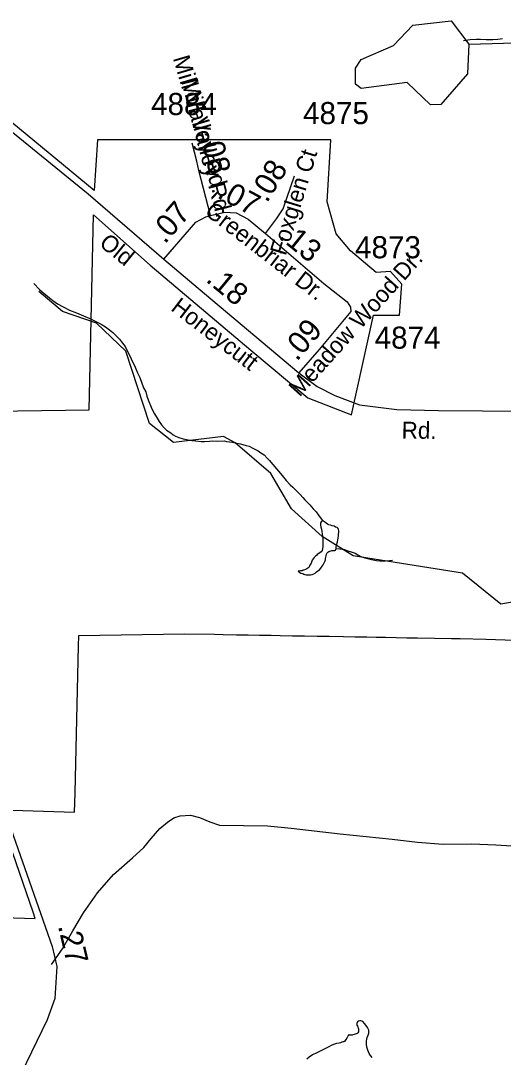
# Model space of a CAD drawing. Extents: x 2001466 to 2224147, y 644118 to 847247.
# Drawn here: x 2068297 to 2071024, y 663505 to 669368 of the extents above; entities that cross this region are included whole.
import ezdxf

# ---------------------------------------------------------------- set-up
doc = ezdxf.new("R2010")
doc.units = 0
for name, color, linetype in [('Exist Boundary Political City Limit New', 7, 'Continuous'), ('Exist Hydrographic Creek Single Shore', 7, 'Continuous'), ('Exist Hydrographic Misc Water Feature', 7, 'Continuous'), ('Exist Road Non-System Type 51', 7, 'Continuous'), ('Exist Road Non-System Type 51 Label', 7, 'Continuous'), ('Exist Road Secondary Mileage Hundredths English Label', 7, 'Continuous'), ('Exist Road Secondary Type 51 Attributed', 7, 'Continuous'), ('Exist Road Secondary Type 51 Label', 7, 'Continuous'), ('Exist Road Secondary Type 51 Number Label', 7, 'Continuous'), ('Map Preparation Boundary City Limit Buffer Line', 7, 'Continuous')]:
    doc.layers.add(name, color=color, linetype=linetype)

msp = doc.modelspace()

# ---------------------------------------------------------------- linework, layer by layer
at = {"layer": 'Exist Boundary Political City Limit New'}
for points in [[(2070028.4, 668344), (2070050.2, 668694), (2068729.9, 668694), (2068710.9, 668408.2), (2068202, 668828.1)], [(2067739.9, 667154.2), (2068682.6, 667166.9), (2068708, 668269.6), (2069029, 667985.2), (2069598, 667503.9), (2069919, 667234.1), (2070167, 667139.3), (2070291, 667702.2), (2070436.9, 667702.2), (2070451.5, 667877.3), (2070385.9, 667950.2), (2070305.6, 667942.9), (2070159.6, 668066.9), (2070079.4, 668161.7), (2070028.4, 668344)], [(2068249.8, 664902.3), (2068601.1, 664891.6), (2068603.8, 665000), (2068614, 665416.3), (2068623.9, 665830), (2068624.9, 665890), (2069222.4, 665900.2), (2069391.6, 665897.2), (2069441.6, 665896.4), (2069516.6, 665895), (2069581.6, 665893.9), (2069646.6, 665892.8), (2069711.5, 665891.6), (2069762.4, 665890.7), (2069832.5, 665889.4), (2069899.9, 665888.2), (2069972.5, 665887), (2070040.6, 665885.8), (2070121.1, 665884.4), (2070186.2, 665883.2), (2070252.1, 665882.1), (2070304.6, 665881.1), (2070357.5, 665880.2), (2070417.9, 665879.1), (2070478.4, 665878.1), (2070538.9, 665876.9), (2070730.5, 665873.6), (2070780.8, 665872.7), (2070926.2, 665870.1), (2071419.1, 665853.6)], [(2067655.1, 664312.7), (2068378.8, 664290), (2068367, 664325.9), (2068251.6, 664659.2)]]:
    msp.add_lwpolyline(points, dxfattribs=at)
at = {"layer": 'Exist Hydrographic Creek Single Shore'}
msp.add_lwpolyline([(2071243.2, 666109.3), (2071010, 666068.1), (2070793.1, 666243.1), (2070176.1, 666340.9), (2070001.2, 666449.5), (2069826.1, 666607.3), (2069709.2, 666806.5), (2069508.2, 666981.1), (2069442.2, 667015.3), (2069159.2, 666981.7), (2069025.1, 667089.4), (2068891.2, 667498.9), (2068724.1, 667656.6), (2068532.2, 667722.7), (2068399.1, 667837)], dxfattribs=at)
at = {"layer": 'Exist Hydrographic Misc Water Feature'}
msp.add_line((2070829.2, 669234.5), (2071504.2, 669253.6), dxfattribs=at)
for points in [[(2070829.2, 669234.5), (2070821.2, 669067.3), (2070671.3, 668893.2), (2070613.3, 668891.1), (2070480.2, 669018.5), (2070221.2, 668984.3), (2070188.2, 669008), (2070188.2, 669099.8), (2070221.2, 669148.4), (2070404.3, 669226.7), (2070512.2, 669342.6), (2070729.3, 669367.7), (2070829.2, 669234.5)], [(2070799, 669256.8), (2070837.2, 669260.7), (2070873.3, 669263), (2070894.8, 669262.9), (2070926.8, 669260.9), (2070948.9, 669260.8), (2070965.1, 669260.8), (2070993, 669263), (2071018.9, 669267.2)], [(2068370, 667880.5), (2068402.2, 667848.4), (2068418, 667834.6), (2068458.4, 667800.6), (2068478.3, 667784.6), (2068504.1, 667766.9), (2068536.3, 667748.6), (2068572.2, 667731), (2068612.4, 667714.7), (2068650.5, 667698.8), (2068686.6, 667683.2), (2068720.4, 667667.2), (2068750.6, 667651.2), (2068776.2, 667637.2), (2068798.4, 667619.2), (2068816.6, 667603.5), (2068836.5, 667585.5), (2068854.7, 667567.3), (2068872.4, 667543.5), (2068886.3, 667525.6), (2068898.6, 667501.4), (2068914.4, 667469.4), (2068926.7, 667441.6), (2068938.6, 667417.5), (2068946.6, 667399.6), (2068957.1, 667375.7), (2068969, 667349.6), (2068991.1, 667291.9), (2069002.8, 667267.8), (2069008.9, 667243.8), (2069017.1, 667223.9), (2069033.1, 667181.7), (2069041.1, 667165.9), (2069053.2, 667143.8), (2069067, 667119.8), (2069079.5, 667100), (2069091.4, 667082.1), (2069107.4, 667064.2), (2069121.1, 667052), (2069145.3, 667036.1), (2069157.2, 667026.2), (2069171.1, 667018), (2069189.4, 667010), (2069215.2, 667002.4), (2069243.7, 666996.5), (2069263.2, 666994.3), (2069285.1, 666990.6), (2069315.5, 666988.4), (2069335.4, 666988.2), (2069363.3, 666990.5), (2069383.2, 666992.4), (2069409.2, 666990.4), (2069447.1, 666990.8), (2069459.4, 666988.5), (2069493.3, 666984.6), (2069517.5, 666978.9), (2069539.2, 666974.8), (2069571.2, 666965.1), (2069587.6, 666961), (2069609.3, 666950.8), (2069637.6, 666935.1), (2069653.4, 666923), (2069671.5, 666913), (2069689.3, 666893.2), (2069701.8, 666881.2), (2069709.4, 666871.2), (2069721.5, 666857.1)], [(2069721.5, 666857.1), (2069773.8, 666795.3), (2069797.6, 666767.3), (2069819.9, 666743.3), (2069833.7, 666729.4), (2069855.8, 666709.4), (2069875.7, 666687.4), (2069890.1, 666671.4), (2069902.2, 666657.4), (2069929.8, 666629.7), (2069949.9, 666607.6), (2069965.9, 666589.7), (2069980.1, 666571.8), (2069989.9, 666557.7), (2070001.5, 666541.3), (2070004.1, 666537.7)], [(2070004.1, 666537.7), (2070001.5, 666541.3), (2069994.2, 666533.9), (2069991.8, 666527.8), (2069990.3, 666515.9), (2069992.2, 666503.8), (2069996.1, 666491.9), (2069997.9, 666477.8), (2070000.2, 666463.7), (2070002.2, 666452), (2070004.5, 666439.9), (2070004.5, 666429.8), (2070004.1, 666418), (2070004.3, 666403.8), (2070004.3, 666393.7), (2070002.4, 666379.7), (2070000.4, 666372), (2069994.2, 666364), (2069982.3, 666353.6), (2069972.5, 666347.8), (2069968.4, 666343.6), (2069962.6, 666339.6), (2069954.4, 666331.9), (2069948.5, 666323.9), (2069944.6, 666315.9), (2069940.3, 666305.6), (2069938.4, 666299.8), (2069934.5, 666293.5), (2069930.4, 666287.6), (2069928.8, 666281.8), (2069924.3, 666275.6), (2069918.6, 666271.6), (2069912.8, 666267.6), (2069906.7, 666263.7), (2069896.6, 666259.5), (2069892.7, 666259.7), (2069886.6, 666255.8), (2069878.6, 666255.8), (2069872.6, 666253.8), (2069864.4, 666253.4), (2069868.5, 666249.6), (2069880.6, 666243.7), (2069890.7, 666241.8), (2069896.6, 666237.6), (2069902.8, 666235.5), (2069910.6, 666233.9), (2069918.6, 666233.9), (2069924.5, 666233.8), (2069934.8, 666233.9), (2069944.4, 666235.6), (2069952.8, 666239.6), (2069960.6, 666243.7), (2069968.4, 666249.8), (2069976.6, 666255.9), (2069984.6, 666262), (2069992.6, 666271.8), (2070000.6, 666281.9), (2070006.5, 666289.9), (2070008.8, 666297.7), (2070012.7, 666306), (2070016.6, 666311.9), (2070018.4, 666317.7), (2070018.4, 666325.8), (2070020.3, 666334.1), (2070022.5, 666341.9), (2070024.4, 666350.1), (2070028.5, 666358), (2070032.2, 666361.9), (2070038.3, 666365.8), (2070048.4, 666370), (2070054.7, 666371.9), (2070066.6, 666372.1), (2070072.5, 666372), (2070076.2, 666373.9), (2070078.5, 666382.1)], [(2070078.5, 666382.1), (2070080.3, 666387.8), (2070082.2, 666401.7), (2070086.5, 666419.8), (2070088.5, 666432), (2070090.2, 666441.9), (2070092, 666455.8), (2070092, 666463.9), (2070094.1, 666473.8), (2070094.3, 666481.9), (2070092.2, 666489.9), (2070090.2, 666495.9), (2070084.4, 666502), (2070076.2, 666504.1), (2070068.4, 666508.1), (2070055.9, 666510), (2070048.1, 666514), (2070038.3, 666515.9), (2070030.1, 666520), (2070022.1, 666526.1), (2070014.1, 666533.7), (2070010, 666538), (2070004.1, 666537.7)], [(2070078.5, 666382.1), (2070100.2, 666380), (2070126.3, 666376), (2070146.2, 666370.2), (2070164.4, 666364.2), (2070186.4, 666356.4), (2070202.1, 666346.3), (2070218.1, 666338.1), (2070230.2, 666334.3), (2070242.3, 666330.4), (2070264.3, 666324.2), (2070278.6, 666320.5), (2070306.5, 666314.2), (2070326.6, 666312.4), (2070342.4, 666312.4), (2070358.4, 666312.4), (2070380.5, 666314.4), (2070398.2, 666316.5)], [(2070283.8, 663502.9), (2070275.1, 663513.1), (2070267.6, 663522.8), (2070261.4, 663535.1), (2070257.5, 663545), (2070253.4, 663561), (2070251.4, 663578.8), (2070251.6, 663595), (2070253.4, 663606.8), (2070255.3, 663617.1), (2070259.4, 663629.1), (2070263.5, 663641), (2070263.2, 663650.8), (2070263.5, 663658.9), (2070261, 663664.9), (2070257.3, 663672.8), (2070253.2, 663679.1), (2070239.3, 663694.9), (2070229.4, 663707), (2070219.4, 663710.9), (2070213.4, 663710.6), (2070205.4, 663708.6), (2070199.3, 663704.7), (2070195.4, 663696.7), (2070195.4, 663686.6), (2070199.5, 663680.7), (2070201.1, 663674.8), (2070203.4, 663670.8), (2070205.2, 663664.8), (2070205.2, 663656.7), (2070205.6, 663649), (2070201.1, 663642.7), (2070197.6, 663638.8), (2070187.6, 663634.7), (2070181.2, 663632.8), (2070173.2, 663630.8), (2070169.3, 663630.5), (2070161.3, 663630.5), (2070155.4, 663630.6), (2070151.5, 663632.8), (2070147.4, 663628.6), (2070143.1, 663620.7), (2070139.2, 663612.8), (2070133.2, 663604.8), (2070129.3, 663596.8), (2070123.6, 663592.8), (2070119.3, 663592.7), (2070111.3, 663590.6), (2070103.5, 663586.6), (2070095.5, 663584.5), (2070081.6, 663582.6), (2070065.2, 663576.5), (2070051.4, 663570.5), (2070037.3, 663564.5), (2070027.2, 663558.4), (2070015.8, 663552.4), (2070001.2, 663544.5), (2069969.4, 663530.2), (2069945.4, 663518.5), (2069927.6, 663506.1), (2069913.8, 663494.5)]]:
    msp.add_lwpolyline(points, dxfattribs=at)
at = {"layer": 'Exist Road Non-System Type 51'}
msp.add_lwpolyline([(2068470.8, 664030.3), (2068532.6, 664119), (2068590.6, 664219.9), (2068650.7, 664322.6), (2068731, 664435), (2068821.1, 664539.2), (2068929.1, 664633), (2068992.3, 664691.7), (2069033.3, 664742.9), (2069082.4, 664797.9), (2069125.2, 664835), (2069161.6, 664858.3), (2069197.9, 664869.5), (2069256, 664874.3), (2069307.7, 664861.3), (2069365.2, 664836.1), (2069420.8, 664817), (2069690.7, 664813.5), (2069824.5, 664800.8), (2070101.8, 664769.2), (2070395.2, 664739.2), (2070538.9, 664722.3), (2070684.6, 664709.3), (2070846.7, 664712.1), (2070982.6, 664707.3), (2071132.3, 664696.3)], dxfattribs=at)
at = {"layer": 'Exist Road Secondary Type 51 Attributed'}
for points in [[(2067446.5, 669206.9), (2067504.2, 669211), (2067569.6, 669203.7), (2067677, 669168.8), (2067771.4, 669122.4), (2067832.4, 669073), (2067915.1, 669006.1), (2068261.4, 668727.3), (2068676.8, 668389.3)], [(2067446.5, 669206.9), (2067474, 669004.1), (2067515.1, 668668.2), (2067591.1, 668254.1), (2067645, 667943.6), (2067664, 667761.9), (2067661.9, 667400.6), (2067667.1, 667003.5), (2067705.1, 666671.8), (2067786.4, 666166.9), (2067860.3, 665913.4), (2068216, 664867.7), (2068474.6, 664130.4), (2068499.9, 664018.4), (2068495.7, 663927.6), (2068489.4, 663836.8), (2068445.1, 663716.3), (2068298.3, 663412.1)], [(2069369.7, 668265.9), (2069356.4, 668317), (2069343, 668368), (2069316.6, 668470.3), (2069303.7, 668521.4), (2069291, 668572.7), (2069278.8, 668624), (2069265.1, 668675)], [(2069679.5, 668163.3), (2069741.8, 668246.7), (2069779.8, 668303.7), (2069843.1, 668489.6)], [(2068676.8, 668389.3), (2069104.8, 668018.5)], [(2069104.8, 668018.5), (2069286.3, 668228.7), (2069343.3, 668259.4), (2069369.7, 668265.9)], [(2069369.7, 668265.9), (2069450.5, 668285.8), (2069514.8, 668280.5), (2069581.3, 668244.6), (2069679.5, 668163.3)], [(2069679.5, 668163.3), (2070010.4, 667881.2), (2070142.4, 667777.7), (2070160.3, 667747.1)], [(2069104.8, 668018.5), (2069335.4, 667824.2), (2069869, 667376.3)], [(2070160.3, 667747.1), (2070161.4, 667722.8), (2069984, 667508.4), (2069869, 667376.3)], [(2069869, 667376.3), (2069971.9, 667298.2), (2070071.1, 667247.5), (2070210.4, 667194.7), (2070421.5, 667169.3), (2070658, 667163), (2071402.1, 667156.6)]]:
    msp.add_lwpolyline(points, dxfattribs=at)
at = {"layer": 'Map Preparation Boundary City Limit Buffer Line'}
for points in [[(2070028.4, 668344), (2070050.2, 668694), (2068729.9, 668694), (2068710.9, 668408.2), (2068202, 668828.1)], [(2067739.9, 667154.2), (2068682.6, 667166.9), (2068708, 668269.6), (2069029, 667985.2), (2069598, 667503.9), (2069919, 667234.1), (2070167, 667139.3), (2070291, 667702.2), (2070436.9, 667702.2), (2070451.5, 667877.3), (2070385.9, 667950.2), (2070305.6, 667942.9), (2070159.6, 668066.9), (2070079.4, 668161.7), (2070028.4, 668344)], [(2068249.8, 664902.3), (2068601.1, 664891.6), (2068603.8, 665000), (2068614, 665416.3), (2068623.9, 665830), (2068624.9, 665890), (2069222.4, 665900.2), (2069391.6, 665897.2), (2069441.6, 665896.4), (2069516.6, 665895), (2069581.6, 665893.9), (2069646.6, 665892.8), (2069711.5, 665891.6), (2069762.4, 665890.7), (2069832.5, 665889.4), (2069899.9, 665888.2), (2069972.5, 665887), (2070040.6, 665885.8), (2070121.1, 665884.4), (2070186.2, 665883.2), (2070252.1, 665882.1), (2070304.6, 665881.1), (2070357.5, 665880.2), (2070417.9, 665879.1), (2070478.4, 665878.1), (2070538.9, 665876.9), (2070730.5, 665873.6), (2070780.8, 665872.7), (2070926.2, 665870.1), (2071419.1, 665853.6)], [(2067655.1, 664312.7), (2068378.8, 664290), (2068367, 664325.9), (2068251.6, 664659.2)]]:
    msp.add_lwpolyline(points, dxfattribs=at)

# ---------------------------------------------------------------- texts
at = {"layer": 'Exist Road Non-System Type 51 Label'}
msp.add_text('Mill Valley Rd.', height=95, rotation=286.38458, dxfattribs=at).set_placement((2069156.1, 669156.4))
at = {"layer": 'Exist Road Secondary Mileage Hundredths English Label'}
for s, rotation, p in [('.08', 284.19732, (2069308.7, 668714.7)), ('.08', 58.47738, (2069688.1, 668333.1)), ('.07', 331.62794, (2069401, 668370.4)), ('.07', 49.18254, (2069111, 668100.6)), ('.13', 321.20533, (2069750.7, 668139.2)), ('.18', 320.4361, (2069337, 667896.3)), ('.09', 49.54111, (2069856.9, 667437.1)), ('.27', 283.25909, (2068506, 664247.3))]:
    msp.add_text(s, height=125, rotation=rotation, dxfattribs=at).set_placement(p)
at = {"layer": 'Exist Road Secondary Type 51 Label'}
for s, rotation, p in [('Mill Valley Rd.', 284.50066, (2069202.9, 669026.6)), ('Foxglen Ct', 73.02092, (2069794.1, 668034.3)), ('Greenbriar Dr.', 322.30155, (2069330.1, 668276.3)), ('Old', 320.89816, (2068734, 668099.1)), ('Meadow Wood Dr.', 48.03362, (2069872.8, 667235.7)), ('Honeycutt', 322.33097, (2069139.3, 667733.4)), ('Rd.', 359.39056, (2070449, 667004.6))]:
    msp.add_text(s, height=95, rotation=rotation, dxfattribs=at).set_placement(p)
at = {"layer": 'Exist Road Secondary Type 51 Number Label'}
for s, p in [('4884', (2069033.3, 668834.2)), ('4875', (2069892.4, 668782.8)), ('4873', (2070186.4, 668024.1)), ('4874', (2070297.2, 667512.7))]:
    msp.add_text(s, height=125, dxfattribs=at).set_placement(p)

doc.saveas('drawing.dxf')
